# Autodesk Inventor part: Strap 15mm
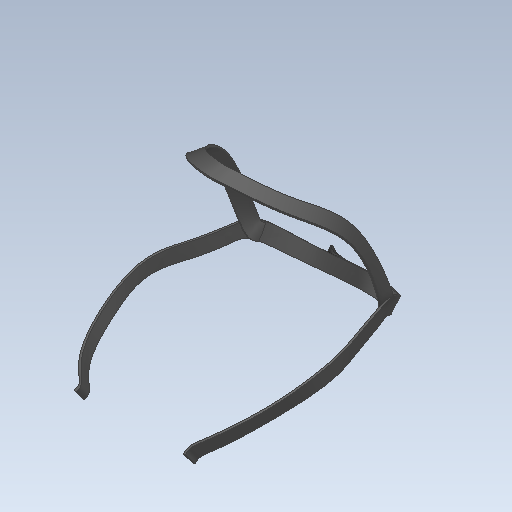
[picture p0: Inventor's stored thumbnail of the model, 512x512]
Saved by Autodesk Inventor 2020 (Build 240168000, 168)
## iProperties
Created: 2021-10
Part Number: Strap 15mm
Material: Steel
Document SubType Name: Modeling
Designer: bruno
Density: 7.85 g/cm^3
Appearance: Par défaut
Author: bruno
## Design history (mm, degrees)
feature "Body1"
node "Solide1"
